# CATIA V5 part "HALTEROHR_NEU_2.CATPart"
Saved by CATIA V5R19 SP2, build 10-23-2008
Part number: P_XXX_HALTEROHR_244_9_12_8,4_LAENGE_P_XXX_SCHEIBE_244_10_8,4_23_4_M8
Description: MOEGLICHE LAENGEN  27 / 33 / 38 / 44 / 48 / 61 / 63 / 72 / 80 / 90 / 100  
Bounding box of the stored display mesh (mm): x -11.497 to 11.497, y -11.493 to 11.493, z -112 to 16
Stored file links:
  C:\Users\Keller\Documents\DEMO_CATIA\HALTEROHR_NEU_2.CATPart
  C:\CATIA\NORMTEILE\Stahlfedern_Halterohr_Fuehrungsrohr\Halterohr_Schraube_Scheibe\HALTEROHR_SCHEIBE.xls
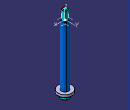
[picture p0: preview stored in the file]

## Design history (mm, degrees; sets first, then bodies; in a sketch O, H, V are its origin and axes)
Parameters
  `244_9` = "ROHR_244_9_12_SCHEIBE_244_10_084_23_4" {design table}
  GEWINDEBESCHREIBUNG = "M8" {design table}
  MASS_HUB = 5 mm
  ROHR_INNEN = 8.4 mm {design table}
  ROHR_AUSSEN = 12 mm {design table}
  ROHRLAENGE1 = 80 mm
  ROHRLAENGE2 = 100 mm
  ROHRLAENGE3 = 60 mm
  SCHEIBE_DICKE = 4 mm {design table}
  SCHEIBE_AUSSEN = 23 mm {design table}
  SCHEIBE_INNEN = 8.4 mm {design table}
  SCHRAUBENGEWINDELAENGE = 16 mm {design table}
  SCHRAUBENGEWINDEDURCHMESSER = 8 mm {design table}
  SCHRAUBENKOPFHOEHE = 8 mm {design table}
  SCHRAUBENKOPFDURCHMESSER = 13 mm {design table}
  SCHRAUBEN_RADIUS = 1 mm {design table}
  SCHRAUBEN_FASE = 1 mm {design table}
  ABZUG_D_1 = 12.5 mm {design table}
  ABZUG_D_2 = 25 mm {design table}
  GEWINDETIEFE = 20 mm {design table}
  BOHRUNGSTIEFE = 24 mm {design table}
AxisSystem1: origin (0, 0, 0), X (1, 0, 0), Y (0, 1, 0), Z (0, 0, 1)
Set1 "Maste_Info"
  Set3 "Abgeh._Geo"
    Set4 "Skizzen_Koerper"
      Sketch1 on YZ plane of AxisSystem1, origin (0, 0, 0), H (0, 1, 0), V (0, 0, 1)
        axis line L1 (0, -78.0323) -> (0, -64.9353)
        point P1 (0, -78.0323)
        point P3 (7.85, -102)
        line L2 (11.5, -100) -> (11.5, -104)
        line L3 (11.5, -104) -> (4.2, -104)
        line L4 (4.2, -104) -> (4.2, -100)
        line L5 (4.2, -100) -> (11.5, -100)
        reference projected line E1 (6, -100) -> (-6, -100) from edge [face of Shaft1 from Sketch2.L2 | face of Shaft1 from Sketch2.L3]
        length L2 = 4 {= SCHEIBE_DICKE}
        distance L5 E1 = 0
        distance L1 L4 = 4.2 {= SCHEIBE_INNEN /2}
        distance L1 L2 = 11.5 {= SCHEIBE_AUSSEN /2}
        coincidence: P1 V
        vertical: L1 V, L2 V, L4 V
        horizontal: L3 H, L5 H
        equidistance: L2 L4 P3, L3 L5 P3
      Sketch2 on YZ plane of AxisSystem1, origin (0, 0, 0), H (0, 1, 0), V (0, 0, 1)
        axis line L1 (0, 24.625) -> (0, -54.8472)
        point P1 (0, 24.625)
        point P3 (5.1, -50)
        line L2 (6, 0) -> (6, -100)
        line L3 (6, -100) -> (4.2, -100)
        line L4 (4.2, -100) -> (4.2, 0)
        line L5 (4.2, 0) -> (6, 0)
        distance L1 L4 = 4.2 {= ROHR_INNEN /2}
        distance L2 L1 = 6 {= ROHR_AUSSEN /2}
        distance L5 H = 0
        length L2 = 100
        length L2 = 100
        coincidence: P1 V
        vertical: L1 V, L2 V, L4 V
        horizontal: L3 H, L5 H
        equidistance: L2 L4 P3, L3 L5 P3
      Sketch3 on YZ plane of AxisSystem1, origin (0, 0, 0), H (0, 1, 0), V (0, 0, 1)
        point P1 (3.25, -108)
        line L1 (6.5, -104) -> (6.5, -111)
        line L2 (5.5, -112) -> (0, -112)
        line L3 (4, -104) -> (6.5, -104)
        point P2 (6.5, -104)
        point P3 (6.5, -112)
        axis line L4 (0, -26.2242) -> (0, -112)
        point P4 (0, -26.2242)
        reference projected line E1 (11.5, -104) -> (-11.5, -104) from edge [face of Shaft2 from Sketch1.L3 | face of Shaft2 from Sketch1.L2]
        arc A1 centre (5.5, -111) radius 1 from (6.5, -111) to (5.5, -112) cw
        line L5 (4, 16) -> (0, 16)
        point P9 (0, 16)
        reference projected line E2 (6, 0) -> (-6, 0) from edge [face of Shaft1 from Sketch2.L5 | face of Shaft1 from Sketch2.L2]
        line L6 (4, 16) -> (4, -104)
        distance L3 E1 = 0
        distance L4 L1 = 6.5 {= SCHRAUBENKOPFDURCHMESSER /2}
        distance P2 P3 = 8 {= SCHRAUBENKOPFHOEHE}
        radius A1 = 1 {= SCHRAUBEN_RADIUS}
        distance L5 E2 = 16 {= SCHRAUBENGEWINDELAENGE}
        distance L6 L4 = 4 {= SCHRAUBENGEWINDEDURCHMESSER /2}
        vertical: L1 V, L4 V, L6 V
        horizontal: L2 H, L3 H, L5 H
        equidistance: L2 L3 P1
        coincidence: P4 V, L1 P3, L2 P3, P9 V
        tangency: A1 L1, A1 L2
Body1 (main body)
  Shaft1: profile Sketch2, axis Sketch2.L1, angle 360
  Sketch4 on XY plane of AxisSystem1, origin (0, 0, 0), H (1, 0, 0), V (0, 1, 0)
    point P1 (70.3564, 15.2272)
    point P2 (0, 0)
    coincidence: P2 O
  UserPattern1: of the body so far, copies 2, at the points of Sketch4, deactivated
Body2
  Shaft2: profile Sketch1, axis Sketch1.L1, angle 360
  UserPattern2: of the body so far, copies 2, at the points of Sketch4, deactivated
Body3
  Shaft3: profile Sketch3, axis Sketch3.L4, angle 360
  UserPattern3: of the body so far, copies 2, at the points of Sketch4, deactivated
  Chamfer1 "SCHRAUBENFASE": length 1 {= SCHRAUBEN_FASE}, angle 45, on edge [face of Shaft3 from Sketch3.L5 | face of Shaft3 from Sketch3.L6]
Body4 "ABZUGSKOERPER_HALTEROHR"
  Sketch5 on ZX plane of AxisSystem1, origin (0, 0, 0), H (1, 0, 0), V (0, 0, 1)
    axis line L1 (0, 16.9793) -> (0, -51.3262)
    point P1 (0, 16.9793)
    line L2 (0, 0) -> (6.25, 0)
    line L3 (6.25, 0) -> (6.25, -95)
    line L4 (6.25, -95) -> (12.5, -95)
    line L5 (12.5, -95) -> (12.5, -195)
    line L6 (12.5, -195) -> (0, -195)
    point P7 (0, -195)
    reference projected line E1 (-8.5, -100) -> (8.5, -100) from edge [face of Shaft2 from Sketch1.L2 | face of Shaft2 from Sketch1.L5]
    distance L3 L1 = 6.25 {= ABZUG_D_1 /2}
    distance L5 L1 = 12.5 {= ABZUG_D_2 /2}
    distance L4 E1 = 5 {= MASS_HUB}
    length L5 = 100
    coincidence: P1 V, P7 L1
    vertical: L1 V, L3 V, L5 V
    horizontal: L2 H, L4 H, L6 H
  Groove1: profile Sketch5, axis Sketch5.L1, angle 360
  Sketch6 on face of Groove1 from Sketch5.L2, origin (-75.215, 25.6591, 0), H (1, 0, 0), V (0, -1, 0)
    point P1 (75.215, 25.6591)
    reference projected point E1 (75.215, 25.6591)
    coincidence: E1 P1
  Hole1 "Bohrung_M8": placed by Sketch6, at (0, 0, 0) direction (0, 0, 1), diameter 6.647, depth 24 {= BOHRUNGSTIEFE}, V-bottom angle 120, threaded "M8", thread diameter 8, thread depth 20 {= GEWINDETIEFE}, pitch 1.25
Relations
  design table, configuration 2, drives `244_9`, GEWINDEBESCHREIBUNG, ROHR_INNEN, ROHR_AUSSEN, SCHEIBE_DICKE, SCHEIBE_AUSSEN, SCHEIBE_INNEN, SCHRAUBENGEWINDELAENGE, SCHRAUBENGEWINDEDURCHMESSER, SCHRAUBENKOPFHOEHE, SCHRAUBENKOPFDURCHMESSER, SCHRAUBEN_RADIUS, SCHRAUBEN_FASE, ABZUG_D_1, ABZUG_D_2, GEWINDETIEFE, BOHRUNGSTIEFE
  Hole1.ThreadDescription = GEWINDEBESCHREIBUNG
  rule:
    /*Regel erzeugt von: KH 11.12.2014*/
    ifSCHRAUBENGEWINDEDURCHMESSER ==6mm
    {Sketch2.length(L2) =ROHRLAENGE1
    	ROHRLAENGE1 .Show=true
    ROHRLAENGE2 .Show=false}
    ifSCHRAUBENGEWINDEDURCHMESSER ==8mm
    {Sketch2.length(L2) =ROHRLAENGE2
    	ROHRLAENGE1 .Show=false
    ROHRLAENGE2 .Show=true}
    ifSCHRAUBENGEWINDEDURCHMESSER ==10mm
    {Sketch2.length(L2) =ROHRLAENGE3
    	ROHRLAENGE1 .Show=false
    	ROHRLAENGE2 .Show=false
    	ROHRLAENGE3 .Show=true}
